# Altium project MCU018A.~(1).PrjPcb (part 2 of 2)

## Sheet MCU018A_ezFET_lite.SchDoc
size 431 x 279 mm; Date: Not shown in title block; ApprovedBy: Not shown in title block; CheckedBy: Not shown in title block; Author: Not shown in title block; CompanyName: Not shown in title block; Engineer: Not shown in title block; Organization: Not shown in title block; Address1: Not shown in title block; Address2: Not shown in title block; Address3: Not shown in title block; Address4: Not shown in title block; DocumentNumber: 4; Revision: Use project parameter SCH_Rev; SheetNumber: 4; SheetTotal: 6; PageSetup: Record=PageOptions¦CenterHorizontal=True¦CenterVertical=True¦PrintScale=1.00¦XCorrection=1.00¦YCorrection=1.00¦PrintKind=0¦BorderSize=5000000¦LeftOffset=0¦BottomOffset=0¦Orientation=2¦PaperLength=1000¦PaperWidth=1000¦Scale=100¦PaperSource=15¦PrintQuality=600¦MediaType=1¦DitherType=10¦PaperKind=Letter¦PrintScaleMode=1; Monkey Man: me
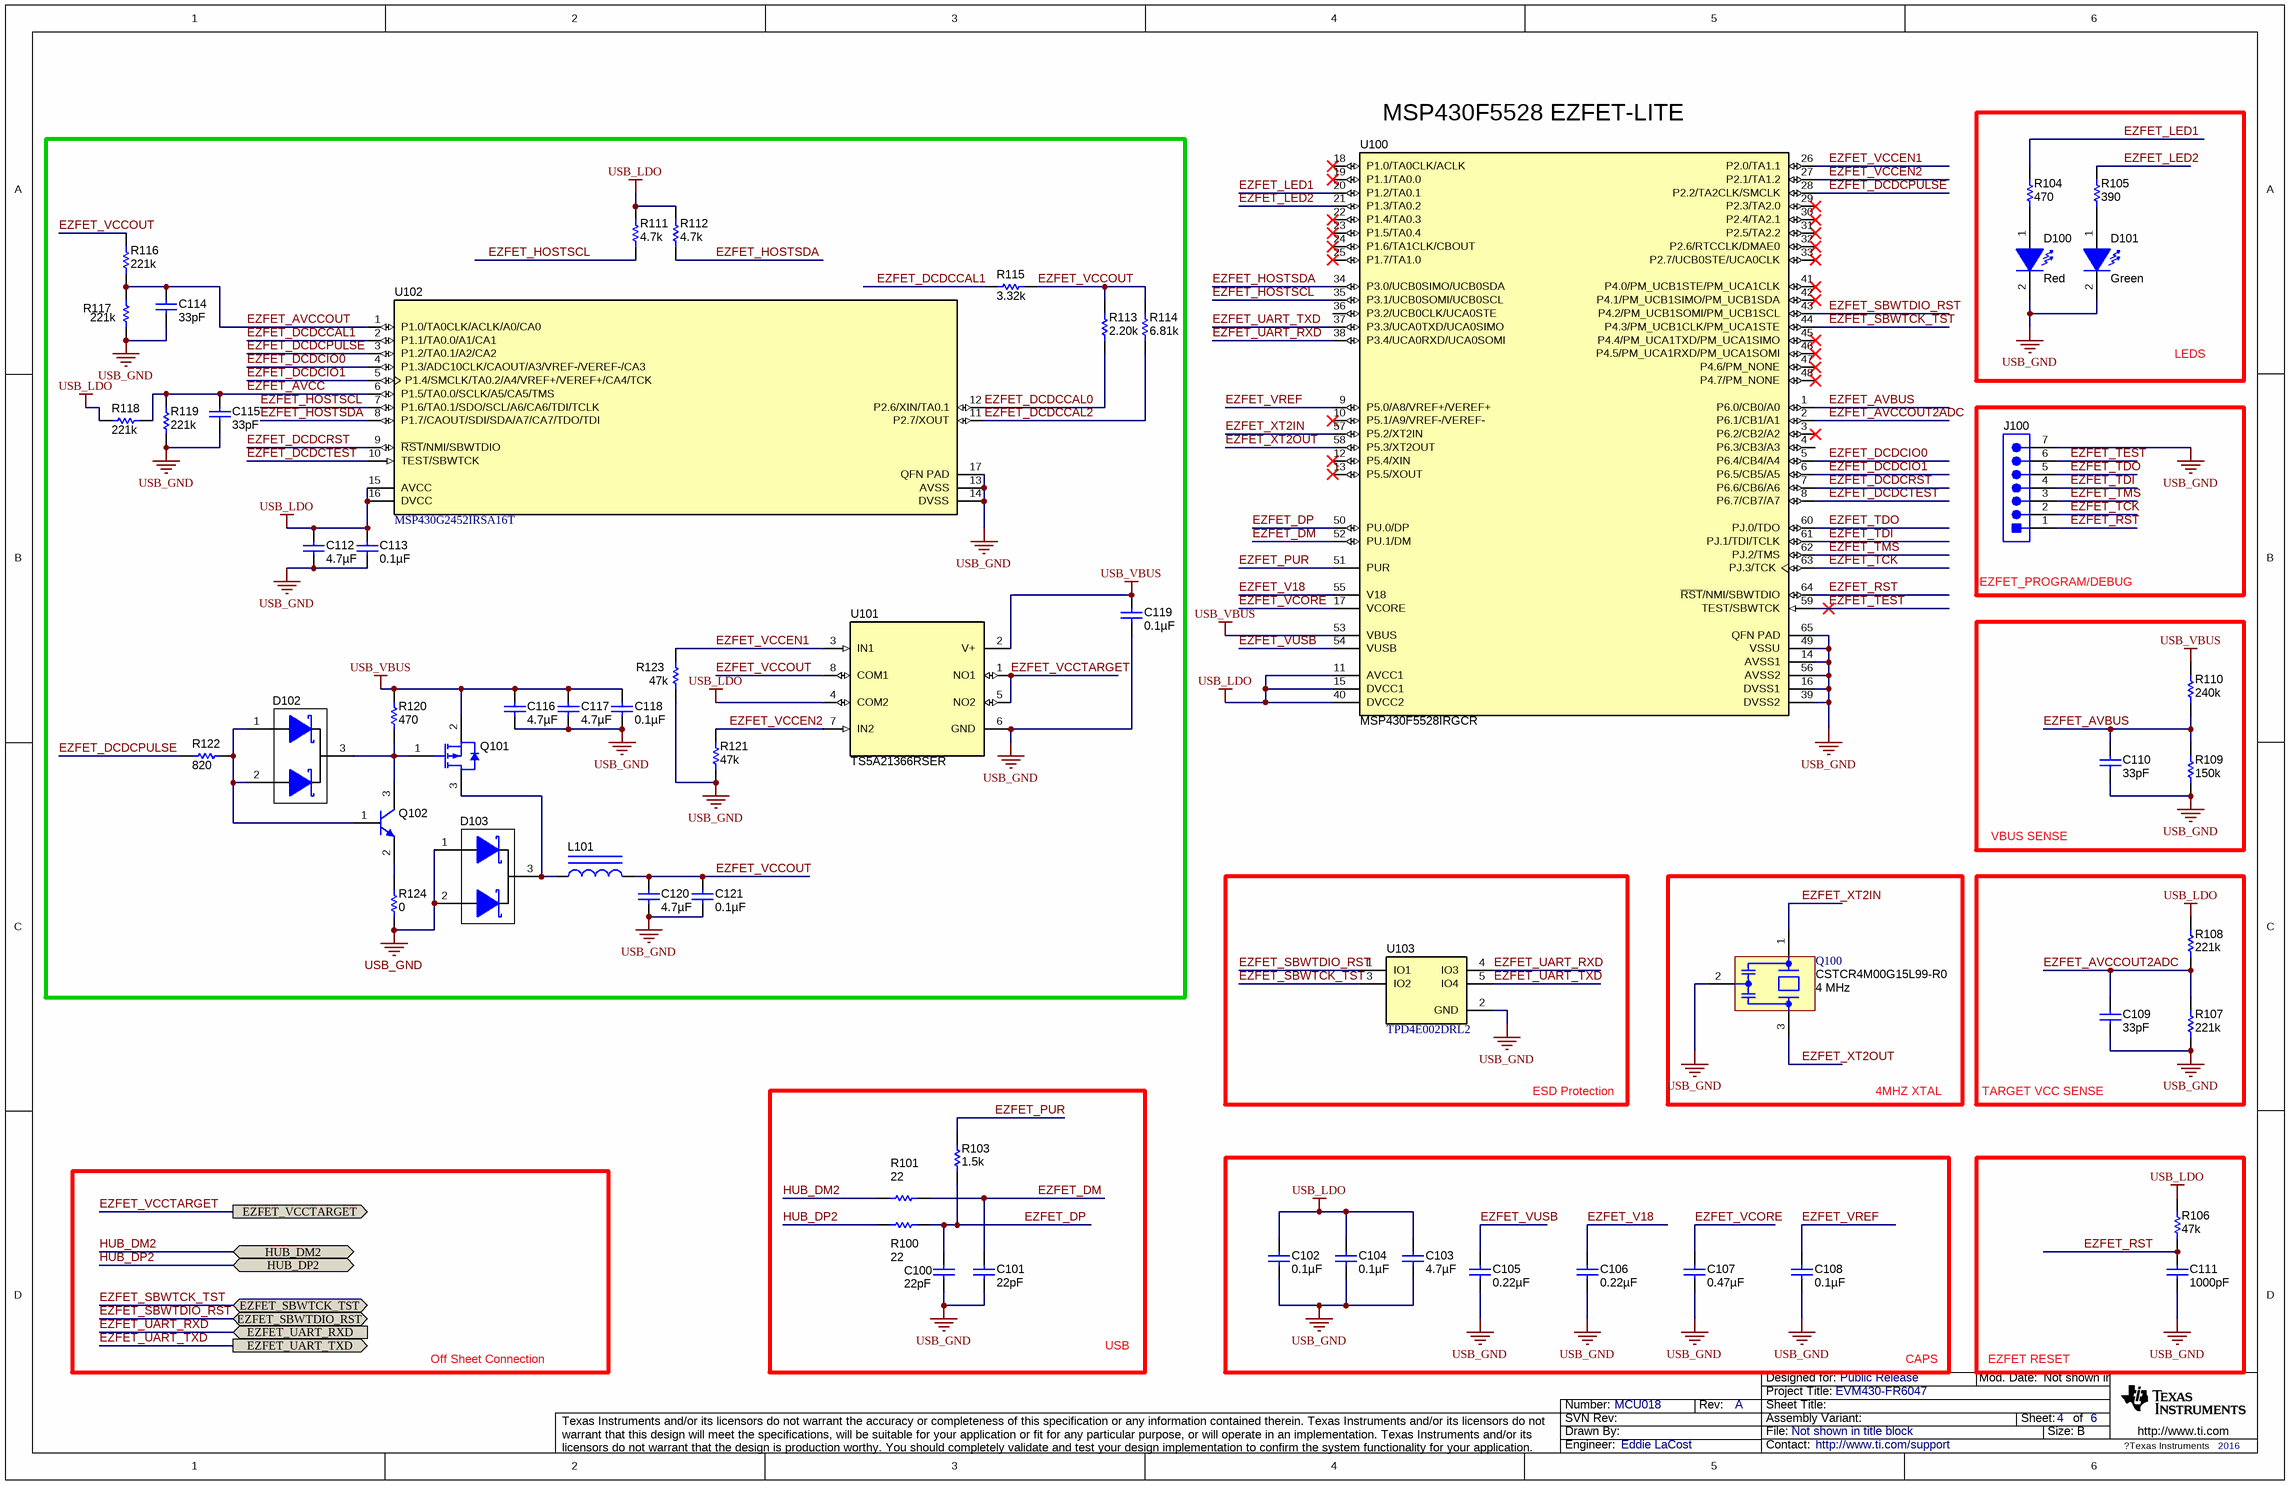
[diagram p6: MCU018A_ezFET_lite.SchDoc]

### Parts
C100  ValueDisplayed: 22pF  [0402S]  (hidden comment: GRM1555C1H220JA01D)
C101  ValueDisplayed: 22pF  [0402S]  (hidden comment: GRM1555C1H220JA01D)
C102  ValueDisplayed: 0.1µF  [0402S]  (hidden comment: GRM155R71C104KA88D)
C103  ValueDisplayed: 4.7µF  [0603S]  (hidden comment: GRM188R61A475MAAJ)
C104  ValueDisplayed: 0.1µF  [0402S]  (hidden comment: GRM155R71C104KA88D)
C105  ValueDisplayed: 0.22µF  [0402S]  (hidden comment: GRM155R71C224KA12D)
C106  ValueDisplayed: 0.22µF  [0402S]  (hidden comment: GRM155R71C224KA12D)
C107  ValueDisplayed: 0.47µF  [0402S]  (hidden comment: GRM155R61C474KE01)
C108  ValueDisplayed: 0.1µF  [0402S]  (hidden comment: GRM155R71C104KA88D)
C109  ValueDisplayed: 33pF  [0402S]  (hidden comment: GRM1555C1H330JA01D)
C110  ValueDisplayed: 33pF  [0402S]  (hidden comment: GRM1555C1H330JA01D)
C111  ValueDisplayed: 1000pF  [0402S]  (hidden comment: GRM1555C1H102JA01D)
C112  ValueDisplayed: 4.7µF  [0603S]  (hidden comment: GRM188R61A475MAAJ)
C113  ValueDisplayed: 0.1µF  [0402S]  (hidden comment: GRM155R71C104KA88D)
C114  ValueDisplayed: 33pF  [0402S]  (hidden comment: GRM1555C1H330JA01D)
C115  ValueDisplayed: 33pF  [0402S]  (hidden comment: GRM1555C1H330JA01D)
C116  ValueDisplayed: 4.7µF  [0603S]  (hidden comment: GRM188R61A475MAAJ)
C117  ValueDisplayed: 4.7µF  [0603S]  (hidden comment: GRM188R61A475MAAJ)
C118  ValueDisplayed: 0.1µF  [0402S]  (hidden comment: GRM155R71C104KA88D)
C119  ValueDisplayed: 0.1µF  [0402S]  (hidden comment: GRM155R71C104KA88D)
C120  ValueDisplayed: 4.7µF  [0603S]  (hidden comment: GRM188R61A475MAAJ)
C121  ValueDisplayed: 0.1µF  [0402S]  (hidden comment: GRM155R71C104KA88D)
D100  value Red  [LED_LTST-C190_Red]  (hidden comment: LTST-C190CKT)
D101  value Green  [LTST-C191_Green]  (hidden comment: LTST-C191TGKT)
D102  BAS40-05-7-F  [SOT-23]  (value not drawn)
D103  BAS40-05-7-F  [SOT-23]  (value not drawn)
J100  PBC07SAAN  [Sullins_xxC07SAAN]  (value not drawn)
L101  CIG21L2R2MNE  [0805]  (value not drawn)
Q100  CSTCR4M00G15L99-R0  Frequency: 4 MHz  [Murata_CSTCR]
Q101  DMG1013UW  [SOT-323]  (value not drawn)
Q102  BC850CLT1G  [SOT-23]  (value not drawn)
R100  ValueDisplayed: 22  [0402S]  (hidden comment: CRCW040222R0JNED)
R101  ValueDisplayed: 22  [0402S]  (hidden comment: CRCW040222R0JNED)
R103  ValueDisplayed: 1.5k  [0402S]  (hidden comment: CRCW04021K50JNED)
R104  value 470  [0402S]  (hidden comment: CRCW0402470RJNED)
R105  value 390  [0402S]  (hidden comment: CRCW0402390RJNED)
R106  value 47k  [0402S]  (hidden comment: CRCW040247K0JNED)
R107  ValueDisplayed: 221k  [0402S]  (hidden comment: CRCW0402221KFKED)
R108  ValueDisplayed: 221k  [0402S]  (hidden comment: CRCW0402221KFKED)
R109  ValueDisplayed: 150k  [0402S]  (hidden comment: CRCW0402150KFKED)
R110  ValueDisplayed: 240k  [0402S]  (hidden comment: CRCW0402240KFKED)
R111  ValueDisplayed: 4.7k  [0402S]  (hidden comment: CRCW04024K70JNED)
R112  ValueDisplayed: 4.7k  [0402S]  (hidden comment: CRCW04024K70JNED)
R113  ValueDisplayed: 2.20k  [0402S]  (hidden comment: CRCW04022K20FKED)
R114  ValueDisplayed: 6.81k  [0402S]  (hidden comment: CRCW04026K81FKED)
R115  ValueDisplayed: 3.32k  [0402S]  (hidden comment: CRCW04023K32FKED)
R116  ValueDisplayed: 221k  [0402S]  (hidden comment: CRCW0402221KFKED)
R117  ValueDisplayed: 221k  [0402S]  (hidden comment: CRCW0402221KFKED)
R118  ValueDisplayed: 221k  [0402S]  (hidden comment: CRCW0402221KFKED)
R119  ValueDisplayed: 221k  [0402S]  (hidden comment: CRCW0402221KFKED)
R120  ValueDisplayed: 470  [0402S]  (hidden comment: CRCW0402470RJNED)
R121  ValueDisplayed: 47k  [0402S]  (hidden comment: CRCW040247K0JNED)
R122  ValueDisplayed: 820  [0402S]  (hidden comment: CRCW0402820RJNED)
R123  ValueDisplayed: 47k  [0402S]  (hidden comment: CRCW040247K0JNED)
R124  ValueDisplayed: 0  [0402S]  (hidden comment: CRCW04020000Z0ED)
U100  MSP430F5528IRGCR  [RGC0064B]
U101  TS5A21366RSER  [RSE0008A]
U102  MSP430G2452IRSA16T  [RSA0016B]
U103  TPD4E002DRL2  [DRL0005A]

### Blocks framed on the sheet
LEDS: D100 D101 R104 R105
EZFET_PROGRAM/DEBUG: J100
VBUS SENSE: C110 R109 R110
ESD Protection: U103
4MHZ XTAL: Q100
TARGET VCC SENSE: C109 R107 R108
USB: C100 C101 R100 R101 R103
CAPS: C102-C108
EZFET RESET: C111 R106

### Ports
EZFET_SBWTCK_TST (bidir), EZFET_SBWTDIO_RST (bidir), EZFET_UART_RXD (in), EZFET_UART_TXD (out), EZFET_VCCTARGET, HUB_DM2 (bidir), HUB_DP2 (bidir)

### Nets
USB_GND: C100.2 C101.2 C102.2 C103.2 C104.2 C105.2 C106.2 C107.2 C108.2 C109.2 C110.2 C111.2 C112.2 C113.2 C114.2 C115.2 C116.2 C117.2 C118.2 C119.2 C120.2 C121.2 D100.2(K) D101.2(K) D103.1(A) D103.2(K) J100.7 Q100.2(GND) R107.1 R109.1 R117.1 R119.1 R121.1 R123.1 R124.2 U100.14(AVSS1) U100.16(DVSS1) U100.39(DVSS2) U100.49(VSSU) U100.56(AVSS2) U100.65(QFN_PAD) U101.6(GND) U102.13(AVSS) U102.14(DVSS) U102.17(QFN_PAD) U103.2(GND)
USB_LDO: C102.1 C103.1 C104.1 C112.1 C113.1 R106.2 R108.2 R111.1 R112.1 R118.1 U100.11(AVCC1) U100.15(DVCC1) U100.40(DVCC2) U101.4(COM2) U102.15(AVCC) U102.16(DVCC)
USB_VBUS: C116.1 C117.1 C118.1 C119.1 Q101.2(S) R110.2 R120.1 U100.53(VBUS) U101.2(V+)
EZFET_AVBUS: C110.1 R109.2 R110.1 U100.1(P6.0/CB0/A0)
EZFET_AVCC: C115.1 R118.2 R119.2 U102.6(P1.5/TA0.0/SCLK/A5/CA5/TMS)
EZFET_AVCCOUT: C114.1 R116.1 R117.2 U102.1(P1.0/TA0CLK/ACLK/A0/CA0)
EZFET_AVCCOUT2ADC: C109.1 R107.2 R108.1 U100.2(P6.1/CB1/A1)
EZFET_DCDCCAL0: R113.1 U102.12(P2.6/XIN/TA0.1)
EZFET_DCDCCAL1: R115.2 U102.2(P1.1/TA0.0/A1/CA1)
EZFET_DCDCCAL2: R114.1 U102.11(P2.7/XOUT)
EZFET_DCDCIO0: U100.5(P6.4/CB4/A4) U102.4(P1.3/ADC10CLK/CAOUT/A3/VREF-/VEREF-/CA3)
EZFET_DCDCIO1: U100.6(P6.5/CB5/A5) U102.5(P1.4/SMCLK/TA0.2/A4/VREF+/VEREF+/CA4/TCK)
EZFET_DCDCPULSE: R122.2 U100.28(P2.2/TA2CLK/SMCLK) U102.3(P1.2/TA0.1/A2/CA2)
EZFET_DCDCRST: U100.7(P6.6/CB6/A6) U102.9(~{RST}/NMI/SBWTDIO)
EZFET_DCDCTEST: U100.8(P6.7/CB7/A7) U102.10(TEST/SBWTCK)
EZFET_DM: C101.1 R101.2 U100.52(PU.1/DM)
EZFET_DP: C100.1 R100.2 R103.2 U100.50(PU.0/DP)
EZFET_HOSTSCL: R111.2 U100.35(P3.1/UCB0SOMI/UCB0SCL) U102.7(P1.6/TA0.1/SDO/SCL/A6/CA6/TDI/TCLK)
EZFET_HOSTSDA: R112.2 U100.34(P3.0/UCB0SIMO/UCB0SDA) U102.8(P1.7/CAOUT/SDI/SDA/A7/CA7/TDO/TDI)
EZFET_LED1: R104.2 U100.20(P1.2/TA0.1)
EZFET_LED2: R105.2 U100.21(P1.3/TA0.2)
EZFET_PUR: R103.1 U100.51(PUR)
EZFET_RST: C111.1 J100.1 R106.1 U100.64(~{RST}/NMI/SBWTDIO)
EZFET_SBWTCK_TST: U100.44(P4.3/PM_UCB1CLK/PM_UCA1STE) U103.3(IO2) ; port EZFET_SBWTCK_TST
EZFET_SBWTDIO_RST: U100.43(P4.2/PM_UCB1SOMI/PM_UCB1SCL) U103.1(IO1) ; port EZFET_SBWTDIO_RST
EZFET_TCK: J100.2 U100.63(PJ.3/TCK)
EZFET_TDI: J100.4 U100.61(PJ.1/TDI/TCLK)
EZFET_TDO: J100.5 U100.60(PJ.0/TDO)
EZFET_TEST: J100.6 U100.59(TEST/SBWTCK)
EZFET_TMS: J100.3 U100.62(PJ.2/TMS)
EZFET_UART_RXD: U100.38(P3.4/UCA0RXD/UCA0SOMI) U103.4(IO3) ; port EZFET_UART_RXD
EZFET_UART_TXD: U100.37(P3.3/UCA0TXD/UCA0SIMO) U103.5(IO4) ; port EZFET_UART_TXD
EZFET_V18: C106.1 U100.55(V18)
EZFET_VCCEN1: R123.2 U100.26(P2.0/TA1.1) U101.3(IN1)
EZFET_VCCEN2: R121.2 U100.27(P2.1/TA1.2) U101.7(IN2)
EZFET_VCCOUT: C120.1 C121.1 L101.2 R113.2 R114.2 R115.1 R116.2 U101.8(COM1)
EZFET_VCCTARGET: U101.1(NO1) U101.5(NO2) ; port EZFET_VCCTARGET
EZFET_VCORE: C107.1 U100.17(VCORE)
EZFET_VREF: C108.1 U100.9(P5.0/A8/VREF+/VEREF+)
EZFET_VUSB: C105.1 U100.54(VUSB)
EZFET_XT2IN: Q100.1(In) U100.57(P5.2/XT2IN)
EZFET_XT2OUT: Q100.3(Out) U100.58(P5.3/XT2OUT)
HUB_DM2: R101.1 ; port HUB_DM2
HUB_DP2: R100.1 ; port HUB_DP2
NetD100_1: D100.1(A) R104.1
NetD101_1: D101.1(A) R105.1
NetD102_1: D102.1(A) D102.2(K) Q102.1(B) R122.1
NetD102_3: D102.3(A) Q101.1(G) Q102.3(C) R120.2
NetD103_3: D103.3(A) L101.1 Q101.3(D)
NetQ102_2: Q102.2(E) R124.1

Not connected (* = marked no-connect by the designer): U100 3(P6.2/CB2/A2)* 4(P6.3/CB3/A3) 10(P5.1/A9/VREF-/VEREF-)* 12(P5.4/XIN)* 13(P5.5/XOUT)* 18(P1.0/TA0CLK/ACLK)* 19(P1.1/TA0.0)* 22(P1.4/TA0.3)* 23(P1.5/TA0.4)* 24(P1.6/TA1CLK/CBOUT)* 25(P1.7/TA1.0)* 29(P2.3/TA2.0)* 30(P2.4/TA2.1)* 31(P2.5/TA2.2)* 32(P2.6/RTCCLK/DMAE0)* 33(P2.7/UCB0STE/UCA0CLK)* 36(P3.2/UCB0CLK/UCA0STE) 41(P4.0/PM_UCB1STE/PM_UCA1CLK)* 42(P4.1/PM_UCB1SIMO/PM_UCB1SDA)* 45(P4.4/PM_UCA1TXD/PM_UCA1SIMO)* 46(P4.5/PM_UCA1RXD/PM_UCA1SOMI)* 47(P4.6/PM_NONE)* 48(P4.7/PM_NONE)*

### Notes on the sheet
- (near U100) MSP430F5528 EZFET-LITE
- Off Sheet Connection

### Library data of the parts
C100 C101 = GRM1555C1H220JA01D: CAP, CERM, 22 pF, 50 V, +/- 5%, C0G/NP0, 0402; Manufacturer: MuRata; Polarized: N; CompType: Capacitor; Value: 22pF; U/M: EA; Cap_F: 0.000000000022; Tolerance_%: 5; Value1: Unknown; VDC_V: 50; Value2: 50V; TaMin_C: -55; TaMax_C: 125; Cap_Case: 0402; AEC Category: Q200
C102 C104 C108 C113 C118 C119 C121 = GRM155R71C104KA88D: CAP, CERM, 0.1 µF, 16 V, +/- 10%, X7R, 0402; Manufacturer: MuRata; Polarized: N; CompType: Capacitor; Value: 0.1uF; U/M: EA; Cap_F: 0.0000001; Tolerance_%: 10; Value1: Unknown; VDC_V: 16; Value2: 16V; TaMin_C: -55; TaMax_C: 125; Cap_Case: 0402
C103 C112 C116 C117 C120 = GRM188R61A475MAAJ: CAP, CERM, 4.7 µF, 10 V, +/- 20%, X5R, 0603; Manufacturer: MuRata; Polarized: N; CompType: Capacitor; Value: 4.7uF; U/M: EA; Cap_F: 0.0000047; Tolerance_%: 20; Value1: Unknown; VDC_V: 10; Value2: 10V; TaMin_C: -55; TaMax_C: 85; Cap_Case: 0603; AEC Category: Q200
C105 C106 = GRM155R71C224KA12D: CAP, CERM, 0.22 µF, 16 V, +/- 10%, X7R, 0402; Manufacturer: MuRata; Polarized: N; CompType: Capacitor; Value: 0.22uF; U/M: EA; Cap_F: 0.00000022; Tolerance_%: 10; Value1: Unknown; VDC_V: 16; Value2: 16V; TaMin_C: -55; TaMax_C: 125; Cap_Case: 0402
C107 = GRM155R61C474KE01: CAP, CERM, 0.47 µF, 16 V, +/- 10%, X5R, 0402; Manufacturer: MuRata; Polarized: N; CompType: Capacitor; Value: 0.47uF; U/M: EA; Cap_F: 0.00000047; Tolerance_%: 10; Value1: Unknown; VDC_V: 16; Value2: 16V; TaMin_C: -55; TaMax_C: 85; Cap_Case: 0402
C109 C110 C114 C115 = GRM1555C1H330JA01D: CAP, CERM, 33 pF, 50 V, +/-5%, C0G/NP0, 0402; Manufacturer: MuRata; Polarized: N; CompType: Capacitor; Value: 33pF; U/M: EA; Cap_F: 0.000000000033; Tolerance_%: 5; Value1: Unknown; VDC_V: 50; Value2: 50V; TaMin_C: -55; TaMax_C: 125; Cap_Case: 0402
C111 = GRM1555C1H102JA01D: CAP, CERM, 1000 pF, 50 V, +/- 5%, C0G/NP0, 0402; Manufacturer: MuRata; Polarized: N; CompType: Capacitor; Value: 1000pF; U/M: EA; Cap_F: 0.000000001; Tolerance_%: 5; Value1: Unknown; VDC_V: 50; Value2: 50V; TaMin_C: -55; TaMax_C: 125; Cap_Case: 0402
D100 = LTST-C190CKT: LED, Red, SMD; Manufacturer: Lite-On; Vf_V: 2; Value2: 2V; Io_A: 0.02; Tjmax_C: 85; Power_TotalModule: 0.0625; Value1: 0.0625W; U/M: EA
D101 = LTST-C191TGKT: LED, Green, SMD; Manufacturer: Lite-On; Type: InGaN; Vf_V: 3.2; Value2: 3.2V; Io_A: 0.02; Value1: W; U/M: EA
D102 D103 = BAS40-05-7-F: Diode, Schottky, 40V, 0.2A, SOT-23; Manufacturer: Diodes Inc.; SymbolCreator: a0412235; U/M: EA; Vf_V: 0.9; Value2: 0.9V; Io_A: 0.2; Vr_V: 40
J100 = PBC07SAAN: Header, 2.54 mm, 7x1, Gold, TH; Manufacturer: Sullins Connector Solutions; SymbolCreator: a0411947; Pitch_mm: 2.54; Gender: Male; Shrouded: N; Row_Count: 1; Current_A: 3; Voltage_V: 1800; Cert_UL: Y
L101 = CIG21L2R2MNE: Inductor, Shielded, Composite, 2.2uH, 0.95A, 0.16 ohm, SMD; Manufacturer: Samsung; Ind_H: 2.2E-6; ValueDisplayed: 2.2µH; Imax_A: 0.95; Irms: 0.95A @ 40C rise; DCR_ohm: 0.16
Q100 = CSTCR4M00G15L99-R0: Resonator, 4MHz, 39pF SMD; Manufacturer: MuRata; SymbolCreator: a0799721; U/M: EA; TaMin_C: 0; TaMax_C: 70; Frequency Stability: ±0.08 %
Q101 = BSS84W-7-F: MOSFET, P-CH, -50V, -0.13A, SOT-323; Manufacturer: Diodes Inc.; Alternate Manufacturer: None; U/M: EA; ChType: P; VdsMax_V: -50; Value1: 10 ohm; Rdson45_Ohm: 10; Value2: ? nC; Vgs_V: -20; IdsMax_A: -0.13
Q102 = BC850CLT1G, ON Semiconductor: Transistor, NPN, 45V, 0.1A, SOT-23; CompType: BJT; PNP: 0; NPN: 1; Vceo_V: 45; Vcesat1_V: 0.7; Value: 0.7V; IcRated_A: 0.1; HfeMax: 800; TaMin_C: -55; TaMax_C: 150; U/M: EA
R100 R101 = CRCW040222R0JNED: RES, 22, 5%, 0.063 W, 0402; Manufacturer: Vishay-Dale; CompType: Resistor; Value_Code: 22R0; Tolerance_%: 5; Power_W: 0.063; Value2: 0.063W; VDC_V: 50; TempCo: 200 ppm/C; EIA_Code: E24; U/M: EA; Value: 22; AEC Category: Q200
R103 = CRCW04021K50JNED: RES, 1.5 k, 5%, 0.063 W, 0402; Manufacturer: Vishay-Dale; CompType: Resistor; Res_ohm: 1500; Value_Code: 1k50; Tolerance_%: 5; Power_W: 0.063; Value2: 0.063W; VDC_V: 50; TempCo: 200 ppm/C; EIA_Code: E24; U/M: EA; Value: 1.5k
R104 = CRCW0402470RJNED: RES, 470, 5%, 0.063 W, 0402; Manufacturer: Vishay-Dale; CompType: Resistor; Value_Code: 470R; Tolerance_%: 5; Power_W: 0.063; Value2: 0.063W; VDC_V: 50; TempCo: 200 ppm/C; EIA_Code: E24; U/M: EA
R105 = CRCW0402390RJNED: RES, 390 ohm, 5%, 0.063W, 0402; Manufacturer: Vishay-Dale; CompType: Resistor; Value_Code: 390R; Tolerance_%: 5; Power_W: 0.063; VDC_V: 50; TempCo: 200 ppm/C; EIA_Code: E24; U/M: EA
R106 = CRCW040247K0JNED: RES, 47 k, 5%, 0.063 W, 0402; Manufacturer: Vishay-Dale; CompType: Resistor; Res_ohm: 47000; Value_Code: 47k0; Tolerance_%: 5; Power_W: 0.063; Value2: 0.063W; VDC_V: 50; TempCo: 200 ppm/C; EIA_Code: E24; U/M: EA
R107 R108 R116-R119 = CRCW0402221KFKED: RES, 221 k, 1%, 0.063 W, 0402; Manufacturer: Vishay-Dale; CompType: Resistor; Res_ohm: 221000; Tolerance_%: 1; Power_W: 0.063; Value2: 0.063W; VDC_V: 50; TempCo: 100 ppm/C; EIA_Code: E96; U/M: EA; Value: 221k; AEC Category: Q200
R109 = CRCW0402150KFKED: RES, 150 k, 1%, 0.063 W, 0402; Manufacturer: Vishay-Dale; CompType: Resistor; Res_ohm: 150000; Tolerance_%: 1; Power_W: 0.063; Value2: 0.063W; VDC_V: 50; TempCo: 100 ppm/C; EIA_Code: E96; U/M: EA; Value: 150k; AEC Category: Q200
R110 = CRCW0402240KFKED: RES, 240 k, 1%, 0.063 W, 0402; Manufacturer: Vishay-Dale; CompType: Resistor; Res_ohm: 240000; Tolerance_%: 1; Power_W: 0.063; Value2: 0.063W; VDC_V: 50; TempCo: 100 ppm/C; U/M: EA; Value: 240k; AEC Category: Q200
R111 R112 = CRCW04024K70JNED: RES, 4.7 k, 5%, 0.063 W, 0402; Manufacturer: Vishay-Dale; CompType: Resistor; Res_ohm: 4700; Value_Code: 4k70; Tolerance_%: 5; Power_W: 0.063; Value2: 0.063W; VDC_V: 50; TempCo: 200 ppm/C; EIA_Code: E24; U/M: EA; Value: 4.7k
R113 = CRCW04022K20FKED: RES, 2.20 k, 1%, 0.063 W, 0402; Manufacturer: Vishay-Dale; CompType: Resistor; Res_ohm: 2200; Value_Code: 2k20; Tolerance_%: 1; Power_W: 0.063; Value2: 0.063W; TempCo: 100 ppm/C; U/M: EA; Value: 2.20k; AEC Category: Q200
R114 = CRCW04026K81FKED: RES, 6.81 k, 1%, 0.063 W, 0402; Manufacturer: Vishay-Dale; CompType: Resistor; Res_ohm: 6810; Value_Code: 6k81; Tolerance_%: 1; Power_W: 0.063; Value2: 0.063W; VDC_V: 50; TempCo: 100 ppm/C; EIA_Code: E96; U/M: EA; Value: 6.81k; AEC Category: Q200
R115 = CRCW04023K32FKED: RES, 3.32 k, 1%, 0.063 W, 0402; Manufacturer: Vishay-Dale; CompType: Resistor; Res_ohm: 3320; Value_Code: 3k32; Tolerance_%: 1; Power_W: 0.063; Value2: 0.063W; VDC_V: 50; TempCo: 100 ppm/C; EIA_Code: E96; U/M: EA; Value: 3.32k; AEC Category: Q200
R120 = CRCW0402470RJNED: RES, 470, 5%, 0.063 W, 0402; Manufacturer: Vishay-Dale; CompType: Resistor; Value_Code: 470R; Tolerance_%: 5; Power_W: 0.063; Value2: 0.063W; VDC_V: 50; TempCo: 200 ppm/C; EIA_Code: E24; U/M: EA; Value: 470
R121 R123 = CRCW040247K0JNED: RES, 47 k, 5%, 0.063 W, 0402; Manufacturer: Vishay-Dale; CompType: Resistor; Res_ohm: 47000; Value_Code: 47k0; Tolerance_%: 5; Power_W: 0.063; Value2: 0.063W; VDC_V: 50; TempCo: 200 ppm/C; EIA_Code: E24; U/M: EA; Value: 47k
R122 = CRCW0402820RJNED: RES, 820, 5%, 0.063 W, 0402; Manufacturer: Vishay-Dale; CompType: Resistor; Value_Code: 820R; Tolerance_%: 5; Power_W: 0.063; Value2: 0.063W; VDC_V: 50; TempCo: 200 ppm/C; EIA_Code: E24; U/M: EA; Value: 820
R124 = CRCW04020000Z0ED: RES, 0, 5%, 0.063 W, 0402; Manufacturer: Vishay-Dale; CompType: Resistor; Value_Code: 0000; Tolerance_%: 5; Power_W: 0.063; Value2: 0.063W; VDC_V: 50; TempCo: 200 ppm/C; EIA_Code: E24; U/M: EA; Value: 0
U100 = MSP430F5528IRGCR: Mixed Signal MicroController, RGC0064B; Manufacturer: Texas Instruments; Alternate PartNumber: MSP430F5528IRGCT; ADC: 12-bit SAR; ADC Channels: 16; Brown Out Reset: Yes; DMA: 3; Eco-Plan: Green (RoHS & no Sb/Br); Flash(KB): 128; Frequency(MHz): 25; GPIO: 47; Multiplier: 32x32; SRAM(B): 8192; SubFamily: 5 Series; Timers - 16-bit: 4; USB: 1; USCI_A (UART/LIN/IrDA/SPI): 2; SymbolCreator: Altium/a0412235; CompType: IC; U/M: EA
U101 = CMP-0074338-2: 0.75-Ohm DUAL SPST ANALOG SWITCH WITH 1.8-V COMPATIBLE INPUT LOGIC, RSE0008A (UQFN-8); Manufacturer: Texas Instruments; SizeZ_mm: 0.6; SizeX_mm: 1.5; SizeArea_mm2: 2.25; CompType: IC; U/M: EA; SizeAreaWB_mm2: 6.25
U102 = CMP-0039612-1: 16 MHz Mixed Signal Microcontroller with 8 KB Flash, 256 B SRAM and 16 GPIOs, 16-pin QFN (RSA), Green (RoHS & no Sb/Br); Manufacturer: Texas Instruments; GPIO: 16; Cap touch I/O: Yes; SRAM(B): 256; ADC: 10-bit SAR; Timers - 16-bit: 1; USI: "(I2C/SPI)","1"; SubFamily: Value Line; ADC Channels: 8
U103 = TPD4E002DRL2: Low-Capacitance Array with + / - 15 kV ESD Protection, 4 Channels, -40 to +85 degC, 5-pin SOT (DRL), Green (RoHS & no Sb/Br); Manufacturer: Texas Instruments; Alternate PartNumber: Equivalent; Breakdown Voltage(Min)(V): 6; IEC 61000-4-2 Air-Gap(+/- kV): 15; IO Capacitance(Typ)(pF): 11; IO Leakage Current(nA): 100; SubFamily: ESD Solution

## Sheet MCU018A_Hardware.SchDoc
size 431 x 279 mm; Date: Not shown in title block; ApprovedBy: Not shown in title block; CheckedBy: Not shown in title block; Author: Not shown in title block; CompanyName: Not shown in title block; Engineer: Not shown in title block; Organization: Not shown in title block; Address1: Not shown in title block; Address2: Not shown in title block; Address3: Not shown in title block; Address4: Not shown in title block; DocumentNumber: 6; Revision: Use project parameter SCH_Rev; SheetNumber: 6; SheetTotal: 6; PageSetup: Record=PageOptions¦CenterHorizontal=True¦CenterVertical=True¦PrintScale=1.00¦XCorrection=1.00¦YCorrection=1.00¦PrintKind=0¦BorderSize=5000000¦LeftOffset=0¦BottomOffset=0¦Orientation=2¦PaperLength=1000¦PaperWidth=1000¦Scale=100¦PaperSource=15¦PrintQuality=600¦MediaType=1¦DitherType=10¦PaperKind=Letter¦PrintScaleMode=1
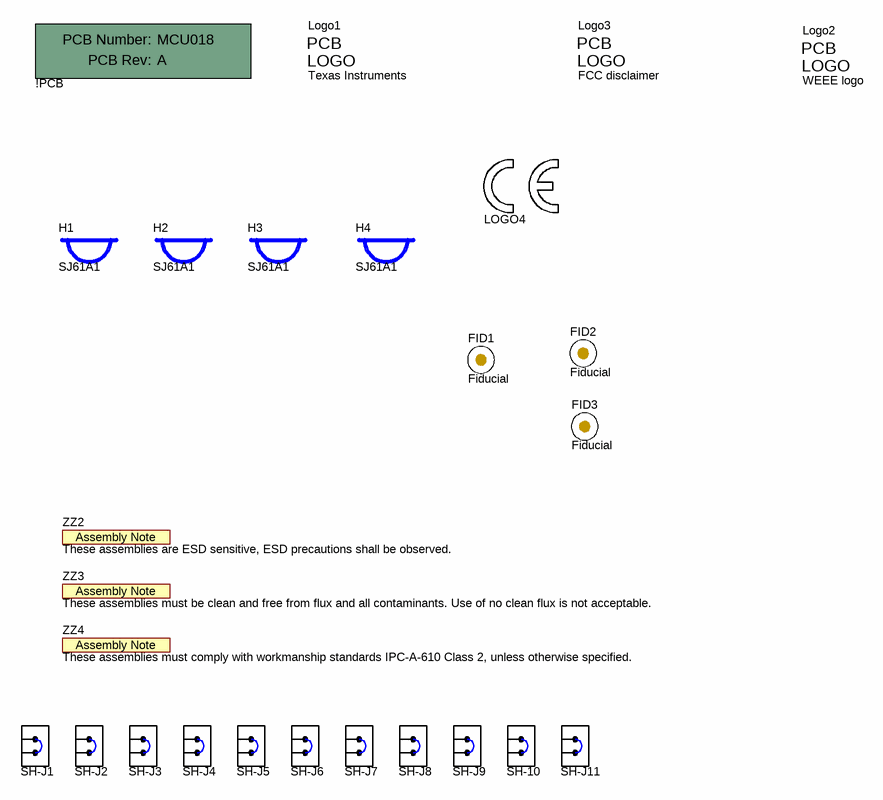
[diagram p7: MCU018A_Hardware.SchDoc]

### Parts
!PCB  Printed Circuit Board  (value not drawn)  (mechanical)
FID1  Fiducial  [Fiducial10-30]
FID2  Fiducial  [Fiducial10-30]
FID3  Fiducial  [Fiducial10-30]
H1  SJ61A1  [Bumpon_SJ61A1]
H2  SJ61A1  [Bumpon_SJ61A1]
H3  SJ61A1  [Bumpon_SJ61A1]
H4  SJ61A1  [Bumpon_SJ61A1]
Logo1  Texas Instruments  [TI_Stacked_Overlay_Small]  (no BOM)
Logo2  WEEE logo  [WEEE_Minimum]  (no BOM)
Logo3  FCC disclaimer  [FCC_disclaimer]  (no BOM)
LOGO4  CE Mark  [CE_Mark_5mm]  (value not drawn)  (no BOM)
SH-10  60900213421  [Wurth_60900213421]  (value not drawn)
SH-J1  60900213421  [Wurth_60900213421]  (value not drawn)
SH-J2  60900213421  [Wurth_60900213421]  (value not drawn)
SH-J3  60900213421  [Wurth_60900213421]  (value not drawn)
SH-J4  60900213421  [Wurth_60900213421]  (value not drawn)
SH-J5  60900213421  [Wurth_60900213421]  (value not drawn)
SH-J6  60900213421  [Wurth_60900213421]  (value not drawn)
SH-J7  60900213421  [Wurth_60900213421]  (value not drawn)
SH-J8  60900213421  [Wurth_60900213421]  (value not drawn)
SH-J9  60900213421  [Wurth_60900213421]  (value not drawn)
SH-J11  60900213421  [Wurth_60900213421]  (value not drawn)
ZZ2  These assemblies are ESD sensitive, ESD precautions shall be observed.  [AssemblyNote]  (no BOM)
ZZ3  These assemblies must be clean and free from flux and all contaminants. Use of no clean flux is not acceptable.  [AssemblyNote]  (no BOM)
ZZ4  These assemblies must comply with workmanship standards IPC-A-610 Class 2, unless otherwise specified.  [AssemblyNote]  (no BOM)

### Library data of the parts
!PCB = PCB: Manufacturer: Any; PartNumber: MCU018; SymbolCreator: a0412235
FID1-FID3 = CMP-0077181-1: Fiducial mark.  There is nothing to buy or mount.
H1-H4 = SJ61A1: Bumpon, Cylindrical, 0.312 X 0.200, Black; Manufacturer: 3M; SymbolCreator: a0412235; Green_Lifecycle: Not Set; Green_REACh: Incomplete
Logo1 = TI_Logo: Texas Instrument Corporate Signature; SymbolCreator: codlsc
Logo2 = CMP-0074769-1
Logo3 = FCC_disclaimer: SymbolCreator: codlsc
LOGO4 = CE Mark: SymbolCreator: a0412235
SH-10 SH-J1-SH-J9 SH-J11 = 60900213421: Shunt, 2.54mm, Gold, Black; Manufacturer: Wurth Elektronik
ZZ2-ZZ4 = AssemblyNote: SymbolCreator: codlsc

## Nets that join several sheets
USB_GND: MCU018A_Comm Interface (28 pins), MCU018A_USB Hub and Pow (31 pins), MCU018A_ezFET_lite (46 pins)
USB_LDO: MCU018A_Comm Interface (12 pins), MCU018A_USB Hub and Pow (12 pins), MCU018A_ezFET_lite (16 pins)
USB_VBUS: MCU018A_Comm Interface (U200.53), MCU018A_USB Hub and Pow (6 pins), MCU018A_ezFET_lite (9 pins)

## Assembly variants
001: not fitted C9 C15 C16 FID1 FID2 FID3 J100 J200 L3 R20 R21 R22 R26 R41 R42 R43 R44 R45 R46 R47 R48 R49 U2 U3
